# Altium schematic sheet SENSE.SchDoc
size 558 x 431 mm; Engineer: Nicholas Oborny; Revision: A.1; Name: Nicholas Oborny; Start Date: 7/23/2012
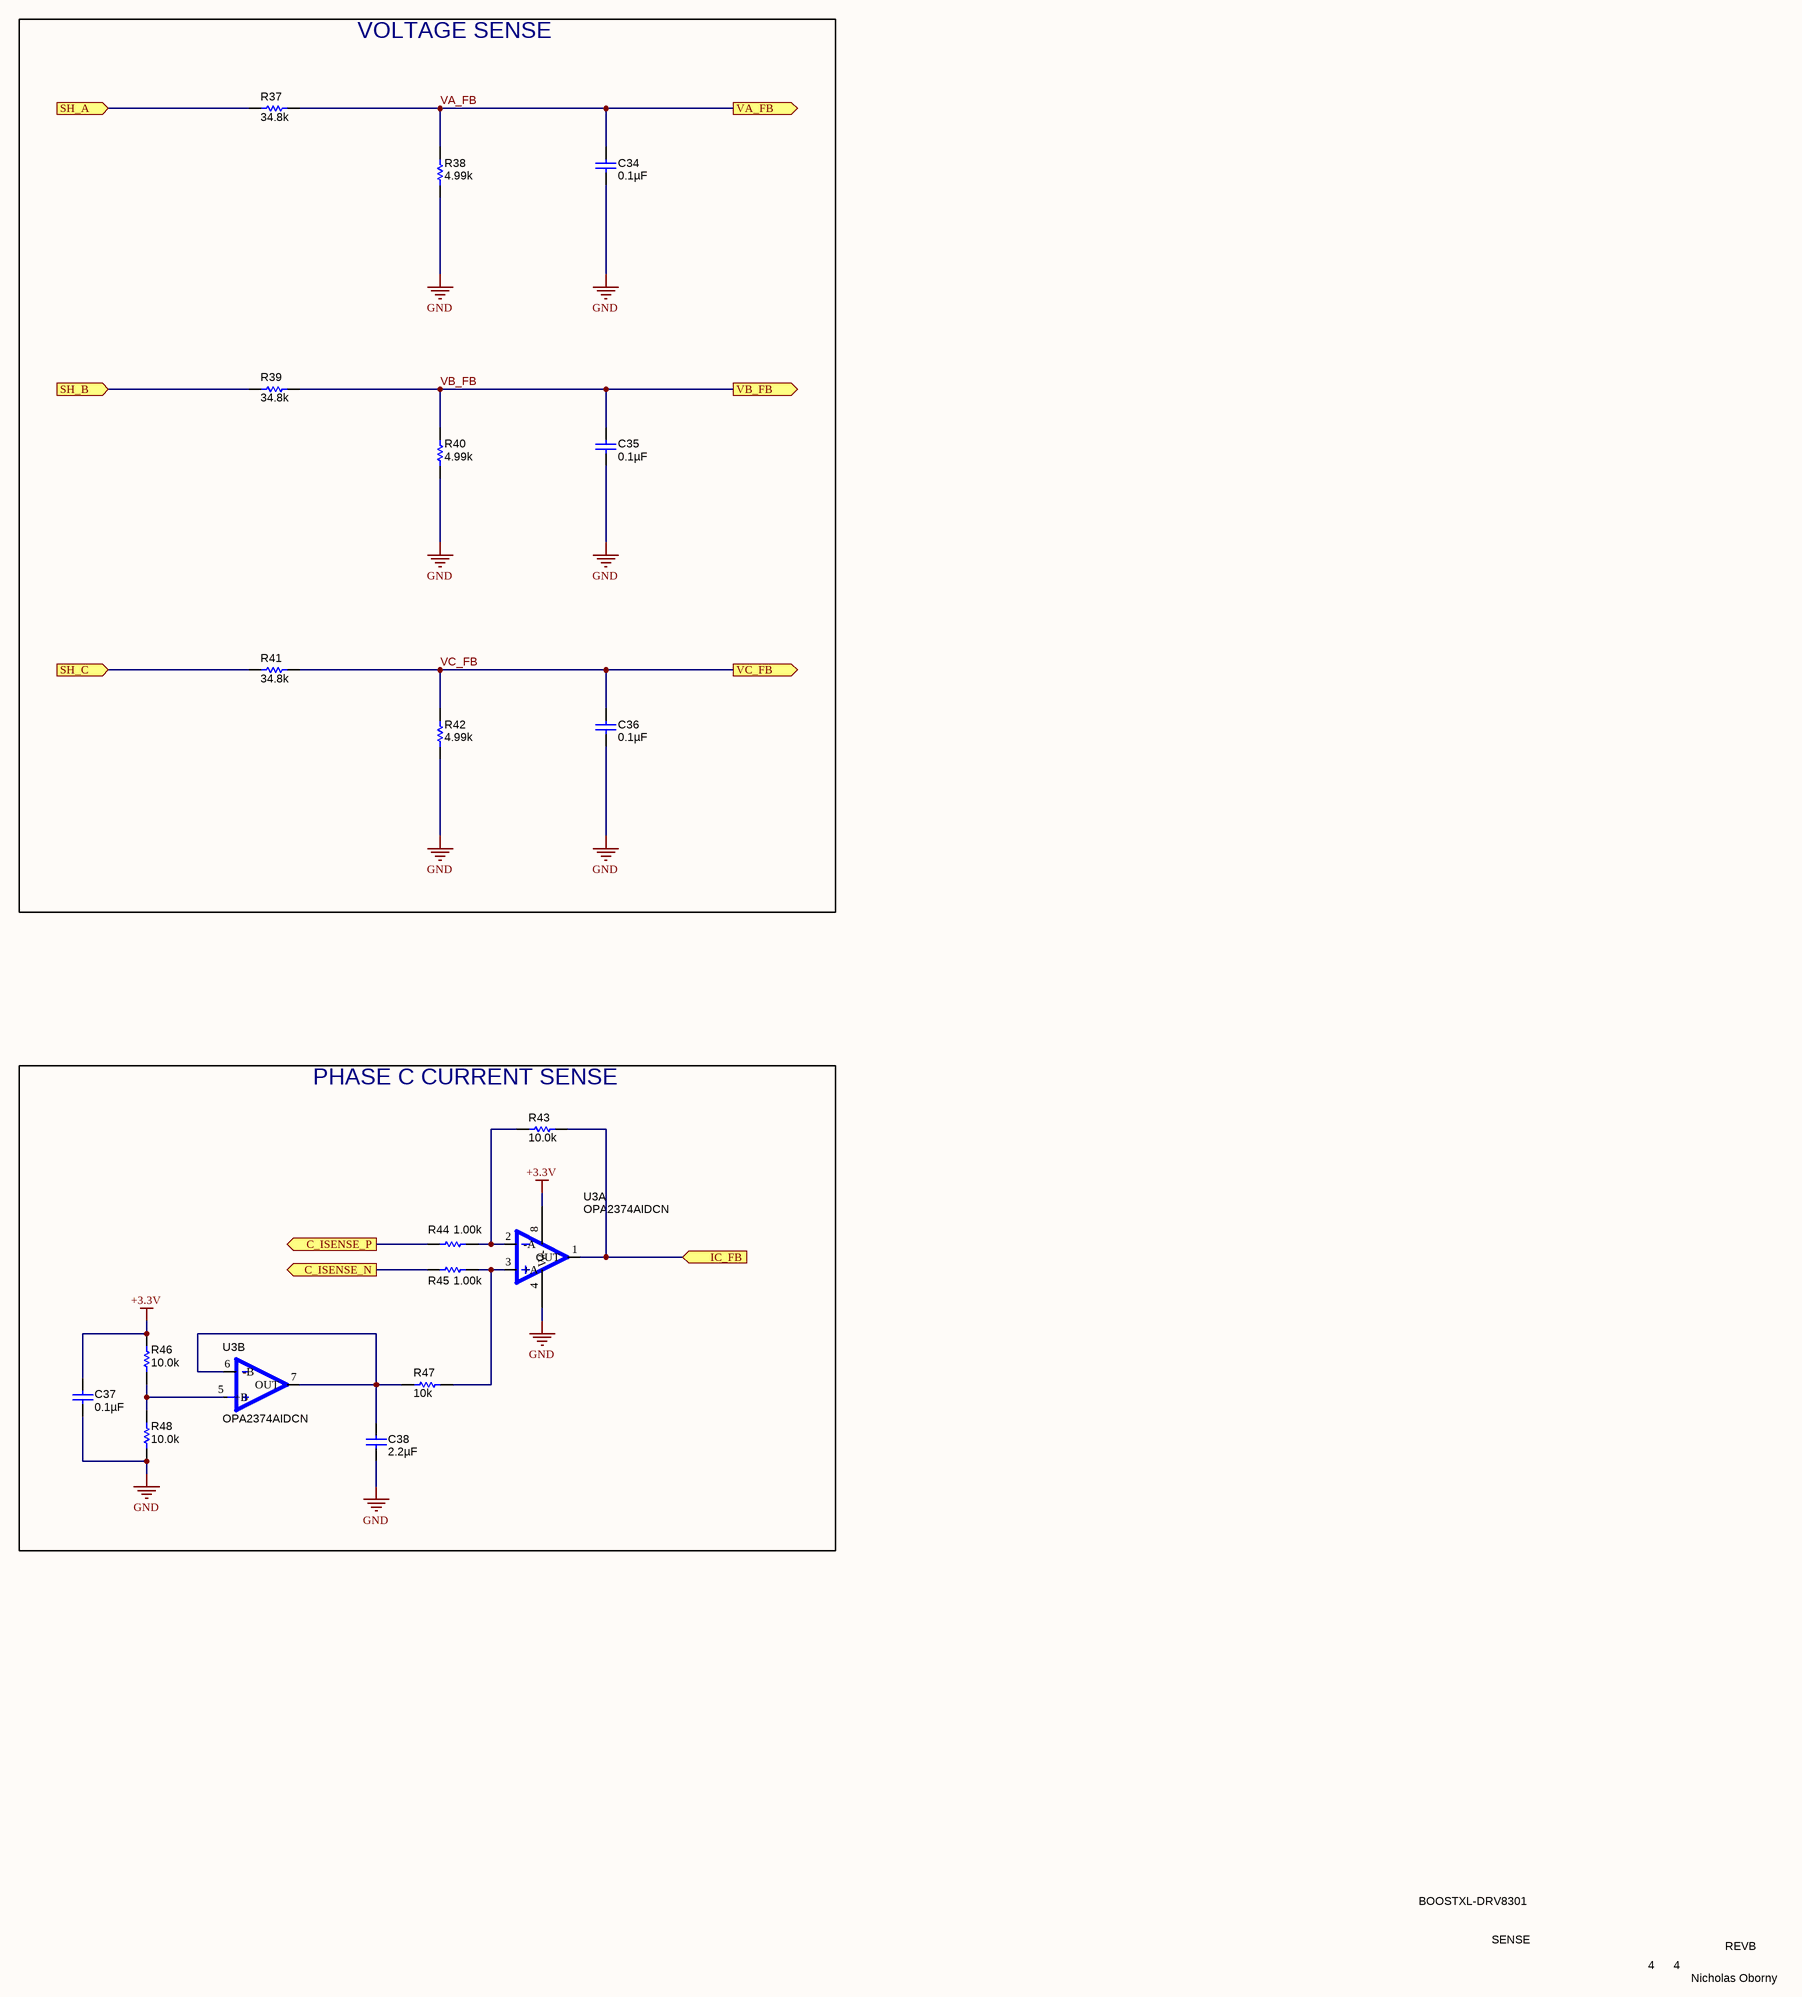
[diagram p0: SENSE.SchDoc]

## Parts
C34  ValueDisplayed: 0.1µF  [0603L]  (hidden comment: C0603C104J4RACTU)
C35  ValueDisplayed: 0.1µF  [0603L]  (hidden comment: C0603C104J4RACTU)
C36  ValueDisplayed: 0.1µF  [0603L]  (hidden comment: C0603C104J4RACTU)
C37  ValueDisplayed: 0.1µF  [0603L]  (hidden comment: C0603C104J4RACTU)
C38  ValueDisplayed: 2.2µF  [0603L]  (hidden comment: C0603C225M8PACTU)
R37  value 34.8k  [0603L]  (hidden comment: CRCW060334K8FKEA)
R38  value 4.99k  [0603L]  (hidden comment: CRCW06034K99FKEA)
R39  value 34.8k  [0603L]  (hidden comment: CRCW060334K8FKEA)
R40  value 4.99k  [0603L]  (hidden comment: CRCW06034K99FKEA)
R41  value 34.8k  [0603L]  (hidden comment: CRCW060334K8FKEA)
R42  value 4.99k  [0603L]  (hidden comment: CRCW06034K99FKEA)
R43  value 10.0k  [0603L]  (hidden comment: RG1608P-103-B-T5)
R44  value 1.00k  [0603L]  (hidden comment: CRCW06031K00FKEA)
R45  value 1.00k  [0603L]  (hidden comment: CRCW06031K00FKEA)
R46  value 10.0k  [0603L]  (hidden comment: RG1608P-103-B-T5)
R47  value 10k  [0603L]  (hidden comment: CRCW060310K0JNEA)
R48  value 10.0k  [0603L]  (hidden comment: RG1608P-103-B-T5)
U3  OPA2374AIDCN  [DCN]  (parts A,B of 2)

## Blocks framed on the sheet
VOLTAGE SENSE: C34-C36 R37-R42
PHASE C CURRENT SENSE: C37 C38 R43-R48 U3

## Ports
C_ISENSE_N, C_ISENSE_P, IC_FB, SH_A, SH_B, SH_C, VA_FB, VB_FB, VC_FB

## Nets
+3.3V: C37.1 R46.2 U3.8(V+)
GND: C34.2 C35.2 C36.2 C37.2 C38.2 R38.1 R40.1 R42.1 R48.1 U3.4(V-)
C_ISENSE_N: R45.1 ; port C_ISENSE_N
C_ISENSE_P: R44.1 ; port C_ISENSE_P
IC_FB: R43.2 U3.1(OUT) ; port IC_FB
SH_A: R37.1 ; port SH_A
SH_B: R39.1 ; port SH_B
SH_C: R41.1 ; port SH_C
VA_FB: C34.1 R37.2 R38.2 ; port VA_FB
VB_FB: C35.1 R39.2 R40.2 ; port VB_FB
VC_FB: C36.1 R41.2 R42.2 ; port VC_FB
NetC38_1: C38.1 R47.1 U3.6(-B) U3.7(OUT)
NetR43_1: R43.1 R44.2 U3.2(-A)
NetR45_2: R45.2 R47.2 U3.3(+A)
NetR46_1: R46.1 R48.2 U3.5(+B)

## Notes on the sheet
- BOOSTXL-DRV8301
- SENSE
- 4
- REVB
- Nicholas Oborny

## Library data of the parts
C34-C37 = C0603C104J4RACTU: CAP, CERM, 0.1uF, 16V, +/-5%, X7R, 0603; Manufacturer: Kemet; Polarized: N; CompType: Capacitor; U/M: EA; Cap_F: 0.0000001; Tolerance_%: 5; Value1: Unknown; VDC_V: 16; TaMin_C: -55; TaMax_C: 125; Cap_Case: 0603
C38 = C0603C225M8PACTU: CAP, CERM, 2.2uF, 10V, +/-20%, X5R, 0603; Manufacturer: Kemet; Polarized: N; CompType: Capacitor; U/M: EA; Cap_F: 0.0000022; Tolerance_%: 20; Value1: Unknown; VDC_V: 10; TaMin_C: -55; TaMax_C: 85; Cap_Case: 0603
R37 R39 R41 = CRCW060334K8FKEA: RES, 34.8k ohm, 1%, 0.1W, 0603; Manufacturer: Vishay-Dale; CompType: Resistor; Res_ohm: 34800; Value_Code: 34k8; Tolerance_%: 1; Power_W: 0.1; VDC_V: 75; TempCo: 100 ppm/C; EIA_Code: E96; U/M: EA
R38 R40 R42 = CRCW06034K99FKEA: RES, 4.99k ohm, 1%, 0.1W, 0603; Manufacturer: Vishay-Dale; CompType: Resistor; Res_ohm: 4990; Value_Code: 4k99; Tolerance_%: 1; Power_W: 0.1; VDC_V: 75; TempCo: 100 ppm/C; EIA_Code: E96; U/M: EA
R43 R46 R48 = RG1608P-103-B-T5: RES, 10.0k ohm, 0.1%, 0.1W, 0603; Manufacturer: Susumu Co Ltd; CompType: Resistor; Res_ohm: 10000; Value_Code: 10k0; Tolerance_%: 0.1; VDC_V: 75; TempCo: 25 ppm/C; EIA_Code: E192; U/M: EA
R44 R45 = CRCW06031K00FKEA: RES, 1.00k ohm, 1%, 0.1W, 0603; Manufacturer: Vishay-Dale; CompType: Resistor; Res_ohm: 1000; Value_Code: 1k00; Tolerance_%: 1; Power_W: 0.1; VDC_V: 75; TempCo: 100 ppm/C; EIA_Code: E96; U/M: EA
R47 = CRCW060310K0JNEA: RES, 10k ohm, 5%, 0.1W, 0603; Manufacturer: Vishay-Dale; CompType: Resistor; Res_ohm: 10000; Value_Code: 10k0; Tolerance_%: 5; Power_W: 0.1; VDC_V: 75; TempCo: 200 ppm/C; EIA_Code: E24; U/M: EA
U3 = OPA2374AIDCN: IC, CMOS, R-R I/O  Op Amp, Single Supply, 6.5MHz, 585uA; Manufacturer: TI; Area: 27000; Value: OPA2374AIDCNx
